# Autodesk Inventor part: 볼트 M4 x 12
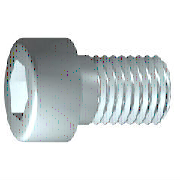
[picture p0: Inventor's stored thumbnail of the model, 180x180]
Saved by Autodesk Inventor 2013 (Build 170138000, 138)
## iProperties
IsCustomPart: 1
Created: 2012-02
Part Number: 볼트 M4 x 12
Material: 스테인리스강
Description: 6각 소켓 머리 캡 나사
Document SubType Name: Modeling
Standard: ISO 4762
Designer: mduedu
Standard Revision: Fourth edition 2004-03-01
Standards Organization: ISO
Language: ko-KR
Size Designation: M4 x 12
Categories: <MemberInstance><Categories><Category DisplayName="조임쇠" InternalName="e4da775c-781d-43d5-af7c-5136215cf5a6" Mnemonic="FSTN"><Category DisplayName="볼트" InternalN
Density: 8.08 g/cm^3
Mass: 2.29719 g
Surface Area: 3.30853 cm^2
Volume: 0.284306 cm^3
Author: mduedu
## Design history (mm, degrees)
sketch "스케치1"
  geometry: L1 (-1, 0)-(12, 0); L2 (12, 0)-(12, 2); L3 (12, 2)-(1.75, 2); L4 (1.75, 2)-(1.32, 2); L5 (1.32, 2)-(0, 2); L6 (0, 2)-(0, 3.5); L7 (0, 3.5)-(-4, 3.5); L8 (-4, 3.5)-(-4, 1.732); L9 (-4, 1.732)-(-2, 1.732); L10 (-2, 1.732)-(-1, 0); L11 (-7.2, 0)-(15.2, 0) reference; L12 (0, -0.7)-(0, 4.2) reference; L13 (1.75, 2)-(0, 2)
  constraints: 22 end point, 6 parallel, 2 collinear, 2 perpendicular, 1 horizontal, 1 point on line
  dimensions: "d1" = 10.25 distance from line of L3.end L2 (= GEL); "d2" = 0.42952 distance of L4.end L3.end (computed from GAL); "d3" = 4 distance between parallel lines of L8 L6 (= KOH); "d4" = 2 distance of L8.end L9.end (= INTI); "d5" = 60 deg angle of L10 L1; "d6" = 4 diameter of L3 L1 (= GD); "d7" = 4 diameter of L5 L1 (= BDM); "d8" = 3.4641 diameter of L9 L1 (= 1.1547 x SW); "d9" = 7 diameter of L7 L1 (= KOD); "d26" = 12 distance between parallel lines of L12 L2 (= NLG)
revolve "본체" sketch "스케치1" stored, may be unused: angle "d10" = 90 deg
sketch "스케치2"
  geometry: L1 (0, -4.9)-(0, 4.9) reference; L2 (-4.9, 0)-(4.9, 0) reference; L3 (1.732, 0)-(0.866, -1.5); L4 (0.866, -1.5)-(-0.866, -1.5); L5 (-0.866, -1.5)-(-1.732, 0); L6 (-1.732, 0)-(-0.866, 1.5); L7 (-0.866, 1.5)-(0.866, 1.5); L8 (0.866, 1.5)-(1.732, 0); 2 further points
  constraints: 12 end point, 1 coincident, 1 horizontal alignment, 1 point on line, 12 other
extrude "슬롯" join sketch "스케치2" stored distance "d11" = 10; taper "d12" = 0 deg
workplane "Work Plane1"
fillet "Fillet2" dims "d30" = 0.1 (= R)
body "Solid1"
fillet "모깎기1" dims "d17" = 0.4 (= RR)
feature "스레드" dims "d13" = 10.25 (= GEL), "d14" = 0
chamfer "모따기1" distance "d15" = 0.42941 (= -0.5 x SPD + 0.5 x GD); stored, may be unused: second distance "d16" = 0.42941 (= GUL), angle "d27" = 45 deg
other parameters: "GD" = 4 [user parameter; used in 2 equation terms], "NLG" = 12 [user parameter; used in 1 equation term], "GEL" = 10.25 [user parameter; used in 2 equation terms], "KOD" = 7 [user parameter; used in 1 equation term], "KOH" = 4 [user parameter; used in 1 equation term], "INTI" = 2 [user parameter; used in 1 equation term], "GAL" = 0.42941 (= 0.61345 x PTC) [user parameter; used in 1 equation term], "GUL" = 0.42941 (= 0.61345 x PTC) [user parameter; used in 1 equation term], "BDM" = 4 (= NND) [user parameter; used in 1 equation term], "SW" = 3 [user parameter; used in 2 equation terms], "RR" = 0.4 [user parameter; used in 1 equation term], "SPD" = 3.14117 (= NND - 1.2269 x PTC) [user parameter; used in 1 equation term], "d19" = 0, "d28" = 0, "d29" = 0, "R" = 0.1 [user parameter; used in 1 equation term], "TOA" = 30 deg [user parameter], "GD1" = 3.14117 (= THREADDIA - 1.2269 x PTC) [user parameter], "THREADDIA" = 4 [user parameter; used in 1 equation term], "FAWI" = 45 deg [user parameter], "TPU" = 14.28571 (computed from PTC) [user parameter], "PTC" = 0.7 [user parameter; used in 5 equation terms], "NND" = 4 [user parameter; used in 2 equation terms], "E0" = 3.465 (= 1.155 x SW) [user parameter]
